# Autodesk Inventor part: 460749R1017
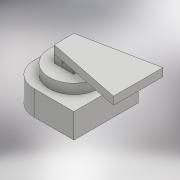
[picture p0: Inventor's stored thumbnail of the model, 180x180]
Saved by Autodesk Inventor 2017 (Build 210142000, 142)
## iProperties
Created: 2016-07
Part Number: 460749R1017
Material: Generic
Document SubType Name: Modeling
Designer: Polytech
Density: 1 g/cm^3
Appearance: Default
Author: Polytech
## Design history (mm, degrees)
sketch "Sketch1"
  geometry: C1 r 23 at (0, 0); 1 further point
  constraints: 1 centre point, 1 coincident
  dimensions: "d0" = 46 diameter of C1
extrude "Extrusion1" new body sketch "Sketch1" distance "d1" = 18; taper "d2" = 0 deg
sketch "Sketch2"
  geometry: L1 (-11.75, 48.75)-(48.75, 48.75); L2 (48.75, 48.75)-(48.75, -48.75); L3 (48.75, -48.75)-(-11.75, -48.75); L4 (-48.75, -11.75)-(-48.75, 11.75); L5 (-48.75, 48.75)-(48.75, -48.75); L6 (48.75, 48.75)-(-48.75, -48.75); A1 r 37 centre (-11.75, 11.75) between (-11.75, 48.75) and (-48.75, 11.75); A2 r 37 centre (-11.75, -11.75) between (-48.75, -11.75) and (-11.75, -48.75); 1 further point
  constraints: 12 end point, 4 point on circle, 4 point on line, 4 tangent, 2 centre point, 2 midpoint, 2 parallel, 1 equal radius, 1 horizontal, 1 perpendicular
  dimensions: "d3" = 97.5 distance of L2.end L6.end; "d4" = 97.5 distance of L1.end L2.end; "d5" = 37 radius of A1 (derived)
extrude "Extrusion2" join sketch "Sketch2" distance "d6" = 37.5; taper "d7" = 0 deg
sketch "Sketch3"
  geometry: C1 r 37.5 at (0, 0); 1 further point
  constraints: 1 centre point, 1 coincident
  dimensions: "d8" = 75 diameter of C1
extrude "Extrusion3" join sketch "Sketch3" distance "d9" = 15; taper "d10" = 0 deg
sketch "Sketch4"
  geometry: L1 (-15, 15)-(15, 15); L2 (15, 15)-(15, -15); L3 (15, -15)-(-15, -15); L4 (-15, -15)-(-15, 15); L5 (-15, 15)-(15, -15); L6 (15, 15)-(-15, -15); 1 further point
  constraints: 12 end point, 2 midpoint, 2 parallel, 1 horizontal, 1 perpendicular
  dimensions: "d11" = 30 distance of L2.end L3.end; "d12" = 30 distance of L1.end L2.end
extrude "Extrusion4" join sketch "Sketch4" distance "d13" = 12; taper "d14" = 0 deg
sketch "Sketch5"
  geometry: L1 (-15, 6)-(15, 6); L2 (15, 6)-(15, -6); L3 (15, -6)-(-15, -6); L4 (-15, -6)-(-15, 6); L5 (-15, 6)-(15, -6); L6 (15, 6)-(-15, -6); 1 further point
  constraints: 12 end point, 2 midpoint, 2 parallel, 1 horizontal, 1 perpendicular
  dimensions: "d15" = 30 distance of L2.end L3.end; "d16" = 12 distance of L1.end L2.end
extrude "Extrusion5" cut sketch "Sketch5" distance "d17" = 12; taper "d18" = 0 deg
sketch "Sketch6"
  geometry: L1 (52.5, 0)-(-22.5, 0) reference; C1 r 3 at (15, 6); 1 further point
  constraints: 1 centre point, 1 vertical alignment
  dimensions: "d19" = 3 radius of C1; "d20" = 6 distance from line of L1 C1.centre
extrude "Extrusion6" cut sketch "Sketch6" stored distance "d21" = 12; taper "d22" = 0 deg
sketch "Sketch7"
  geometry: L1 (-15, 15)-(-15, -15); L2 (-15, -15)-(97.5, -37.5); L3 (97.5, -37.5)-(97.5, 37.5); L4 (97.5, 37.5)-(-15, 15); 4 further points
  constraints: 8 end point, 2 coincident, 1 horizontal alignment, 1 midpoint, 1 parallel, 1 vertical
  dimensions: "d23" = 75 distance of L2.end L3.end; "d24" = 97.5 distance from line of L3 point (0, 0)
extrude "Extrusion7" join sketch "Sketch7" distance "d25" = 12; taper "d26" = 0 deg
sketch "Sketch8"
  geometry: C1 r 23 at (0, 0); 1 further point
  constraints: 1 centre point, 1 coincident
  dimensions: "d27" = 46 diameter of C1
extrude "Extrusion8" cut sketch "Sketch8" distance "d28" = 24.5; taper "d29" = 0 deg
body "Solid1"
